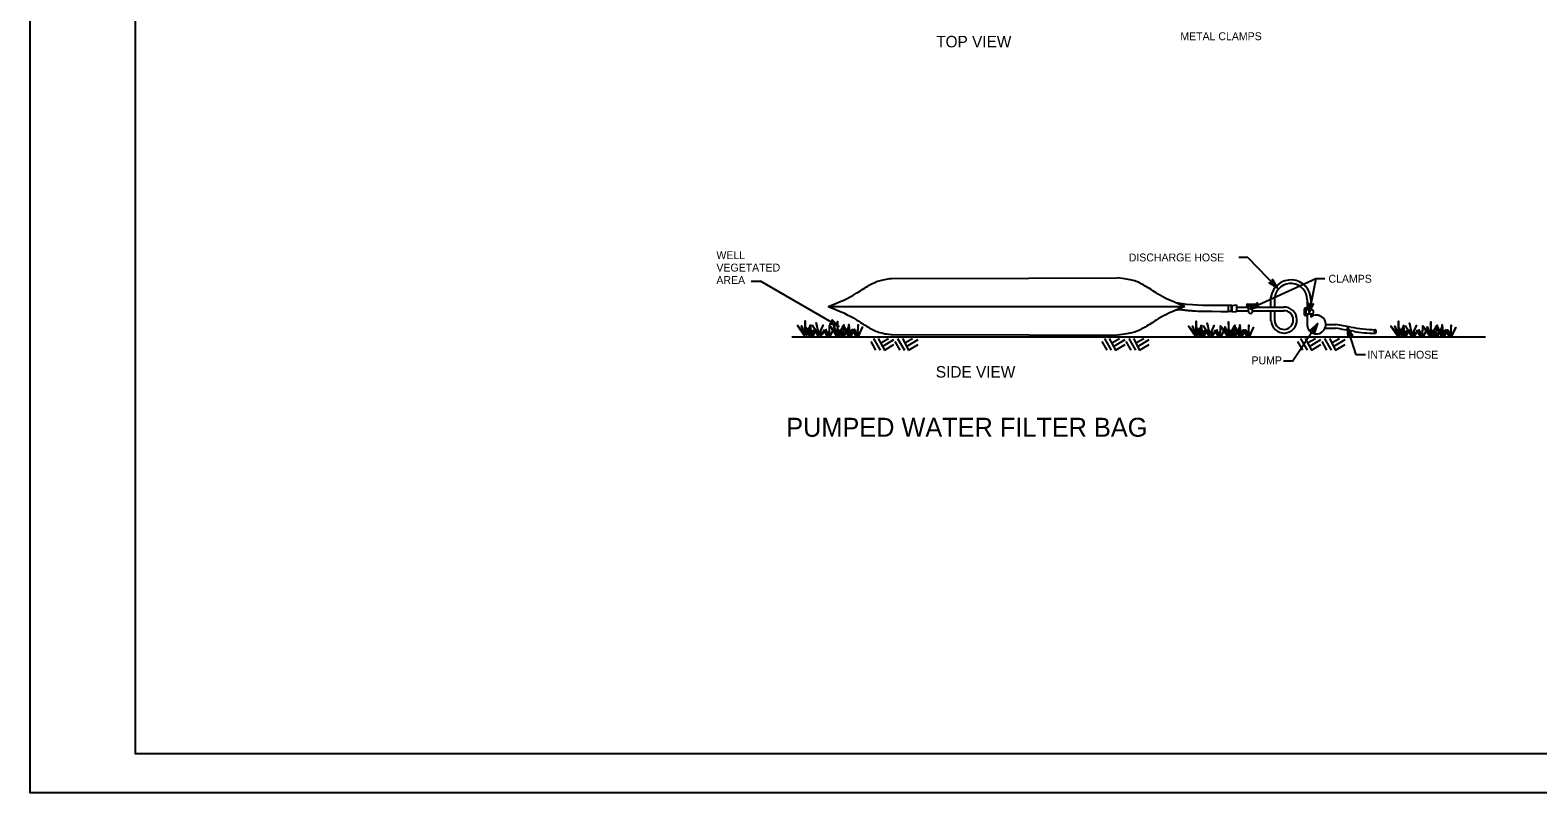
# Model space of a CAD drawing. Extents: x 636462 to 637367, y 299944 to 300538.
# Drawn here: x 636462 to 637035, y 299944 to 300234 of the extents above; entities that cross this region are included whole.
import ezdxf

# ---------------------------------------------------------------- set-up
doc = ezdxf.new("R2010")
doc.units = 0
for name, color, linetype in [('1', 7, 'Continuous'), ('Default', 7, 'Continuous'), ('PLT-BNDY', 7, 'Continuous')]:
    doc.layers.add(name, color=color, linetype=linetype)

# ---------------------------------------------------------------- blocks, each defined once
blk = doc.blocks.new('Group3')
at = {"layer": 'Default'}
for points in [[(7.465, 1.976), (7.424, 2.068), (7.472, 1.977), (7.471, 2.092), (7.483, 1.978), (7.502, 2.036), (7.488, 1.979), (7.531, 2.043), (7.493, 1.975)], [(7.572, 1.973), (7.633, 2.048), (7.566, 1.995), (7.605, 2.091), (7.56, 2.006), (7.533, 2.117), (7.558, 1.989), (7.492, 2.087), (7.553, 1.975)], [(7.676, 1.975), (7.717, 2.064), (7.668, 1.974), (7.669, 2.089), (7.657, 1.975), (7.638, 2.033), (7.652, 1.976), (7.609, 2.04), (7.645, 1.975)], [(7.765, 1.976), (7.809, 2.085), (7.757, 1.996), (7.753, 2.131), (7.749, 2.007), (7.714, 2.078), (7.749, 1.989), (7.674, 2.081), (7.745, 1.976)]]:
    blk.add_lwpolyline(points, dxfattribs=at)

msp = doc.modelspace()

# ---------------------------------------------------------------- linework, layer by layer
at = {"layer": '1'}
msp.add_lwpolyline([(637287.91, 299959.45), (637287.91, 300523.45), (636501.91, 300523.45), (636501.91, 299959.45), (637287.91, 299959.45), (637287.91, 299985.81), (637087.91, 299985.81), (637087.91, 300050.49), (637287.91, 300050.49), (637287.91, 300079.45), (637087.91, 300079.45), (637087.91, 299959.45), (637166.72, 299959.45), (637166.72, 299985.81), (637166.72, 299959.45), (637243.72, 299959.45), (637243.72, 299985.81), (637243.72, 299973.49), (637287.91, 299973.49)], dxfattribs=at)
at = {"layer": 'Default'}
for p, q in [((636925.21, 300148.01), (636921.71, 300148.01)), ((636925.21, 300148.01), (636936.36, 300136.51)), ((636789.69, 300140.04), (636841.86, 300140.08)), ((636841.86, 300140.18), (636875.4, 300140.21)), ((636950.99, 300139.92), (636926.11, 300128.42)), ((636950.99, 300139.92), (636948.51, 300127.07)), ((636954.49, 300139.92), (636950.99, 300139.92)), ((636736.26, 300138.96), (636739.76, 300138.96)), ((636769.63, 300121.8), (636739.76, 300138.96)), ((636765.53, 300129.36), (636841.87, 300129.36)), ((636841.87, 300129.36), (636901.24, 300129.36)), ((636901.79, 300130.18), (636897.93, 300130.72)), ((636904.1, 300129.98), (636901.79, 300130.18)), ((636908.05, 300129.72), (636904.1, 300129.98)), ((636917.64, 300129.72), (636908.05, 300129.72)), ((636919.11, 300129.72), (636917.64, 300129.72)), ((636917.67, 300129.72), (636917.67, 300127.5)), ((636918.86, 300129.72), (636918.86, 300127.5)), ((636919.11, 300129.72), (636920.81, 300129.94)), ((636919.14, 300129.73), (636919.14, 300127.5)), ((636920.81, 300129.16), (636925.41, 300129.16)), ((636920.85, 300129.94), (636920.85, 300127.29)), ((636924.7, 300129.87), (636924.7, 300129.92)), ((636925.03, 300130.24), (636927.35, 300130.24)), ((636925.41, 300129.55), (636925.03, 300129.55)), ((636925.41, 300127.5), (636925.41, 300129.55)), ((636925.41, 300129.55), (636926.97, 300129.55)), ((636926.97, 300127.5), (636926.97, 300129.55)), ((636927.35, 300129.55), (636926.97, 300129.55)), ((636926.97, 300129.16), (636938.84, 300129.16)), ((636927.67, 300129.87), (636927.67, 300129.92)), ((636933.98, 300129.16), (636933.98, 300132.91)), ((636935.38, 300129.16), (636935.38, 300133.01)), ((636946.72, 300126.13), (636946.72, 300128.45)), ((636947.41, 300128.45), (636947.41, 300128.06)), ((636947.74, 300131.84), (636947.74, 300128.06)), ((636949.14, 300131.84), (636949.14, 300128.06)), ((636919.14, 300127.5), (636917.67, 300127.5)), ((636919.14, 300127.5), (636920.85, 300127.29)), ((636920.85, 300127.76), (636925.41, 300127.76)), ((636926.16, 300126.75), (636926.22, 300126.75)), ((636926.97, 300127.76), (636938.84, 300127.76)), ((636933.98, 300123.87), (636933.98, 300127.76)), ((636935.38, 300123.97), (636935.38, 300127.76)), ((636942.21, 300108.61), (636951.63, 300122.9)), ((636947.41, 300126.51), (636947.41, 300128.06)), ((636949.46, 300128.06), (636947.41, 300128.06)), ((636949.46, 300126.51), (636947.41, 300126.51)), ((636947.41, 300126.51), (636947.41, 300126.13)), ((636947.74, 300126.51), (636947.74, 300122.21)), ((636949.14, 300126.51), (636949.14, 300125.36)), ((636751.72, 300117.79), (637015.53, 300117.79)), ((636782.75, 300117.19), (636785.27, 300112.79)), ((636782.75, 300117.19), (636785.27, 300112.79)), ((636784.55, 300117.19), (636786.95, 300112.79)), ((636784.55, 300117.19), (636786.95, 300112.79)), ((636785.5, 300115.51), (636788.45, 300117.19)), ((636785.5, 300115.51), (636788.45, 300117.19)), ((636789.69, 300118.67), (636841.86, 300118.63)), ((636791.92, 300117.19), (636794.49, 300112.79)), ((636791.92, 300117.19), (636794.49, 300112.79)), ((636793.77, 300117.19), (636796.09, 300112.79)), ((636793.77, 300117.19), (636796.09, 300112.79)), ((636794.64, 300115.51), (636797.64, 300117.19)), ((636794.64, 300115.51), (636797.64, 300117.19)), ((636841.86, 300118.63), (636875.4, 300118.51)), ((636870.67, 300117.19), (636873.2, 300112.79)), ((636870.67, 300117.19), (636873.2, 300112.79)), ((636872.47, 300117.19), (636874.87, 300112.79)), ((636872.47, 300117.19), (636874.87, 300112.79)), ((636873.42, 300115.51), (636876.37, 300117.19)), ((636873.42, 300115.51), (636876.37, 300117.19)), ((636879.84, 300117.19), (636882.41, 300112.79)), ((636879.84, 300117.19), (636882.41, 300112.79)), ((636881.69, 300117.19), (636884.01, 300112.79)), ((636881.69, 300117.19), (636884.01, 300112.79)), ((636882.56, 300115.51), (636885.56, 300117.19)), ((636882.56, 300115.51), (636885.56, 300117.19)), ((636945.17, 300117.19), (636947.69, 300112.79)), ((636945.17, 300117.19), (636947.69, 300112.79)), ((636946.96, 300117.19), (636949.36, 300112.79)), ((636946.96, 300117.19), (636949.36, 300112.79)), ((636947.91, 300115.51), (636950.86, 300117.19)), ((636947.91, 300115.51), (636950.86, 300117.19)), ((636954.33, 300117.19), (636956.91, 300112.79)), ((636954.33, 300117.19), (636956.91, 300112.79)), ((636954.56, 300121.18), (636958.51, 300121.08)), ((636954.82, 300122.57), (636958.63, 300122.48)), ((636956.18, 300117.19), (636958.51, 300112.79)), ((636956.18, 300117.19), (636958.51, 300112.79)), ((636957.06, 300115.51), (636960.06, 300117.19)), ((636957.06, 300115.51), (636960.06, 300117.19)), ((636966.38, 300111.04), (636963.13, 300121.32)), ((636781.7, 300116.01), (636783.55, 300112.79)), ((636781.7, 300116.01), (636783.55, 300112.79)), ((636786.17, 300114.16), (636790.55, 300116.76)), ((636786.17, 300114.16), (636790.55, 300116.76)), ((636786.95, 300112.79), (636790.55, 300114.94)), ((636786.95, 300112.79), (636790.55, 300114.94)), ((636790.85, 300116.01), (636792.72, 300112.79)), ((636790.85, 300116.01), (636792.72, 300112.79)), ((636795.37, 300114.16), (636799.74, 300116.76)), ((636795.37, 300114.16), (636799.74, 300116.76)), ((636796.09, 300112.79), (636799.74, 300114.94)), ((636796.09, 300112.79), (636799.74, 300114.94)), ((636869.62, 300116.01), (636871.47, 300112.79)), ((636869.62, 300116.01), (636871.47, 300112.79)), ((636874.09, 300114.16), (636878.47, 300116.76)), ((636874.09, 300114.16), (636878.47, 300116.76)), ((636874.87, 300112.79), (636878.47, 300114.94)), ((636874.87, 300112.79), (636878.47, 300114.94)), ((636878.77, 300116.01), (636880.64, 300112.79)), ((636878.77, 300116.01), (636880.64, 300112.79)), ((636883.29, 300114.16), (636887.66, 300116.76)), ((636883.29, 300114.16), (636887.66, 300116.76)), ((636884.01, 300112.79), (636887.66, 300114.94)), ((636884.01, 300112.79), (636887.66, 300114.94)), ((636944.12, 300116.01), (636945.96, 300112.79)), ((636944.12, 300116.01), (636945.96, 300112.79)), ((636948.59, 300114.16), (636952.96, 300116.76)), ((636948.59, 300114.16), (636952.96, 300116.76)), ((636949.36, 300112.79), (636952.96, 300114.94)), ((636949.36, 300112.79), (636952.96, 300114.94)), ((636953.26, 300116.01), (636955.13, 300112.79)), ((636953.26, 300116.01), (636955.13, 300112.79)), ((636957.78, 300114.16), (636962.15, 300116.76)), ((636957.78, 300114.16), (636962.15, 300116.76)), ((636958.51, 300112.79), (636962.15, 300114.94)), ((636958.51, 300112.79), (636962.15, 300114.94)), ((636942.21, 300108.61), (636938.71, 300108.61)), ((636969.88, 300111.04), (636966.38, 300111.04))]:
    msp.add_line(p, q, dxfattribs=at)
for points in [[(636934.54, 300139.26), (636934.51, 300139.61), (636936.36, 300136.51), (636934.54, 300139.26), (636934.42, 300138.86), (636936.36, 300136.51), (636934.05, 300138.48), (636933.65, 300138.35), (636936.36, 300136.51), (636933.27, 300138.37), (636933.65, 300138.35)], [(636765.53, 300129.36), (636767.84, 300128.44), (636769.79, 300127.63), (636771.42, 300126.9), (636772.78, 300126.25), (636773.92, 300125.66), (636774.88, 300125.13), (636775.7, 300124.64), (636776.44, 300124.18), (636777.13, 300123.74), (636777.79, 300123.33), (636778.41, 300122.94), (636779, 300122.57), (636779.57, 300122.22), (636780.11, 300121.88), (636780.64, 300121.57), (636781.15, 300121.27), (636781.64, 300120.98), (636782.13, 300120.72), (636782.62, 300120.47), (636783.11, 300120.23), (636783.61, 300120.01), (636784.12, 300119.81), (636784.65, 300119.63), (636785.2, 300119.46), (636785.79, 300119.3), (636786.4, 300119.16), (636787.07, 300119.03), (636787.79, 300118.92), (636788.57, 300118.81), (636789.42, 300118.7), (636789.69, 300118.67)], [(636929.3, 300129.22), (636929.64, 300129.13), (636926.11, 300128.42), (636929.3, 300129.22), (636928.97, 300129.47), (636926.11, 300128.42), (636928.74, 300129.94), (636928.74, 300130.36), (636926.11, 300128.42), (636928.89, 300130.71), (636928.74, 300130.36)], [(636949.73, 300130.13), (636949.99, 300130.35), (636948.51, 300127.07), (636949.73, 300130.13), (636949.32, 300130), (636948.51, 300127.07), (636948.81, 300130.09), (636948.47, 300130.34), (636948.51, 300127.07), (636948.27, 300130.67), (636948.47, 300130.34)], [(636757.21, 300118.21), (636758.87, 300122.26), (636756.93, 300118.98), (636756.78, 300123.96), (636756.64, 300119.37), (636755.35, 300122), (636756.65, 300118.72), (636753.89, 300122.11), (636756.49, 300118.22)], [(636767.15, 300123.97), (636767.03, 300124.29), (636769.63, 300121.8), (636767.15, 300123.97), (636767.14, 300123.54), (636769.63, 300121.8), (636766.88, 300123.09), (636766.54, 300122.85), (636769.63, 300121.8), (636766.16, 300122.78), (636766.54, 300122.85)], [(636897.93, 300128.03), (636898.05, 300128.06), (636898.16, 300128.08), (636898.27, 300128.11), (636898.37, 300128.13), (636898.47, 300128.15), (636898.56, 300128.16), (636898.64, 300128.18), (636898.73, 300128.19), (636898.8, 300128.2), (636898.88, 300128.21), (636898.95, 300128.22), (636899.02, 300128.23), (636899.09, 300128.24), (636899.15, 300128.24), (636899.22, 300128.24), (636899.28, 300128.25), (636899.35, 300128.25), (636899.42, 300128.24), (636899.5, 300128.24), (636899.58, 300128.24), (636899.68, 300128.23), (636899.79, 300128.22), (636899.92, 300128.2), (636900.07, 300128.18), (636900.24, 300128.16), (636900.43, 300128.14), (636900.64, 300128.11), (636900.86, 300128.08), (636901.1, 300128.05), (636901.35, 300128.02), (636901.61, 300127.99), (636901.88, 300127.96), (636902.15, 300127.93), (636902.44, 300127.9), (636902.74, 300127.87), (636903.06, 300127.84), (636903.42, 300127.81), (636903.81, 300127.78), (636904.25, 300127.75), (636904.74, 300127.71), (636905.31, 300127.68), (636906.1, 300127.64), (636907.29, 300127.6), (636909.04, 300127.57), (636911.52, 300127.54), (636914.89, 300127.51), (636917.67, 300127.5)], [(636905.97, 300118.05), (636907.62, 300122.09), (636905.68, 300118.81), (636905.54, 300123.79), (636905.39, 300119.21), (636904.11, 300121.83), (636905.4, 300118.56), (636902.64, 300121.94), (636905.25, 300118.05)], [(636949.36, 300120.52), (636949.03, 300120.41), (636951.63, 300122.9), (636949.36, 300120.52), (636949.78, 300120.48), (636951.63, 300122.9), (636950.23, 300120.21), (636950.45, 300119.85), (636951.63, 300122.9), (636950.51, 300119.48), (636950.45, 300119.85)], [(636982.89, 300118.05), (636984.54, 300122.09), (636982.6, 300118.81), (636982.46, 300123.79), (636982.32, 300119.21), (636981.03, 300121.83), (636982.32, 300118.56), (636979.57, 300121.94), (636982.17, 300118.05)], [(636771.77, 300118.26), (636773.26, 300121.55), (636771.45, 300118.21), (636771.5, 300122.45), (636771.05, 300118.24), (636770.36, 300120.37), (636770.88, 300118.28), (636769.29, 300120.65), (636770.62, 300118.25)], [(636773.12, 300118.25), (636771.6, 300121.64), (636773.4, 300118.3), (636773.37, 300122.54), (636773.79, 300118.32), (636774.49, 300120.45), (636773.97, 300118.36), (636775.57, 300120.72), (636774.16, 300118.21)], [(636777.12, 300118.26), (636778.61, 300121.55), (636776.8, 300118.21), (636776.86, 300122.45), (636776.4, 300118.24), (636775.71, 300120.37), (636776.23, 300118.28), (636774.64, 300120.65), (636775.98, 300118.25)], [(636920.52, 300118.09), (636922.02, 300121.38), (636920.2, 300118.05), (636920.26, 300122.29), (636919.81, 300118.07), (636919.12, 300120.21), (636919.63, 300118.11), (636918.05, 300120.48), (636919.38, 300118.08)], [(636921.88, 300118.08), (636920.36, 300121.48), (636922.15, 300118.13), (636922.12, 300122.37), (636922.55, 300118.15), (636923.25, 300120.28), (636922.72, 300118.19), (636924.32, 300120.55), (636922.91, 300118.05)], [(636925.87, 300118.09), (636927.37, 300121.38), (636925.55, 300118.05), (636925.61, 300122.29), (636925.16, 300118.07), (636924.47, 300120.21), (636924.98, 300118.11), (636923.4, 300120.48), (636924.73, 300118.08)], [(636963.48, 300118.04), (636963.34, 300117.72), (636963.13, 300121.32), (636963.48, 300118.04), (636963.78, 300118.34), (636963.13, 300121.32), (636964.27, 300118.5), (636964.69, 300118.43), (636963.13, 300121.32), (636965.01, 300118.24), (636964.69, 300118.43)], [(636997.44, 300118.09), (636998.94, 300121.38), (636997.12, 300118.05), (636997.18, 300122.29), (636996.73, 300118.07), (636996.04, 300120.21), (636996.55, 300118.11), (636994.97, 300120.48), (636996.3, 300118.08)], [(636998.8, 300118.08), (636997.28, 300121.48), (636999.07, 300118.13), (636999.04, 300122.37), (636999.47, 300118.15), (637000.17, 300120.28), (636999.64, 300118.19), (637001.24, 300120.55), (636999.83, 300118.05)], [(637002.8, 300118.09), (637004.29, 300121.38), (637002.47, 300118.05), (637002.53, 300122.29), (637002.08, 300118.07), (637001.39, 300120.21), (637001.9, 300118.11), (637000.32, 300120.48), (637001.65, 300118.08)]]:
    msp.add_lwpolyline(points, dxfattribs=at)
for centre, radius, start, end in [((636941.52, 300131.85), 7.62, 359.96051, 171.95351), ((636941.51, 300131.85), 6.24, 359.93949, 169.27656), ((636925.03, 300129.92), 0.325, 90, 180), ((636925.03, 300129.87), 0.325, 180, 270), ((636927.35, 300129.92), 0.325, 360, 90), ((636927.35, 300129.87), 0.325, 270, 0), ((636938.92, 300124.22), 4.95, 183.97483, 91.25762), ((636947.04, 300128.45), 0.325, 90, 180), ((636947.09, 300128.45), 0.325, 360, 90), ((636926.16, 300127.5), 0.75, 180, 270), ((636926.22, 300127.5), 0.75, 270, 0), ((636938.92, 300124.22), 3.55, 183.97483, 91.25762), ((636947.04, 300126.13), 0.325, 180, 270), ((636947.09, 300126.13), 0.325, 270, 0), ((636951.27, 300122.52), 3.55, 183.97483, 127.00163), ((636949.46, 300127.31), 0.75, 360, 90), ((636949.46, 300127.26), 0.75, 270, 360), ((636926.61, 299910.74), 212.74, 79.51504, 81.37638), ((636926.61, 299910.74), 214.14, 79.84955, 81.40009), ((636974.6, 300174.4), 53.86, 259.02396, 268.98442), ((636974.6, 300174.4), 55.26, 260.33279, 268.98442)]:
    msp.add_arc(centre, radius, start, end, dxfattribs=at)
msp.add_ellipse((636973.64, 300119.86), major_axis=(-0.012, -0.699), ratio=0.344138, dxfattribs=at)
for points in [[(636765.53, 300129.36), (636772.21, 300131.93), (636776.87, 300134.77), (636781.28, 300137.62), (636784.64, 300139.3), (636787.77, 300139.83), (636789.69, 300140.04)], [(636901.24, 300129.36), (636894.56, 300131.93), (636889.9, 300134.77), (636885.5, 300137.62), (636881.87, 300139.43), (636878.24, 300139.95), (636875.4, 300140.21)], [(636901.24, 300129.36), (636894.56, 300126.79), (636889.9, 300123.94), (636885.5, 300121.09), (636881.87, 300119.28), (636878.24, 300118.77), (636875.4, 300118.51)]]:
    msp.add_open_spline(points, degree=3, dxfattribs=at)
at = {"layer": 'PLT-BNDY'}
msp.add_lwpolyline([(636461.91, 300538.45), (637302.91, 300538.45), (637302.91, 299944.45), (636461.91, 299944.45)], close=True, dxfattribs=at)

# ---------------------------------------------------------------- block references
at = {"layer": 'Default', "xscale": 36.88524000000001, "yscale": 36.88524000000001}
for p in [(636483.15, 300045.12), (636631.9, 300044.95), (636708.82, 300044.95)]:
    msp.add_blockref('Group3', p, dxfattribs=at)

# ---------------------------------------------------------------- texts
at = {"layer": 'Default'}
for s, height, p in [('TOP VIEW', 4.372, (636806.61, 300227.89)), ('METAL CLAMPS ', 2.998, (636899.48, 300230.62)), ('WELL', 2.998, (636722.99, 300147.4)), ('VEGETATED', 2.998, (636722.99, 300142.66)), ('DISCHARGE HOSE', 2.998, (636879.86, 300146.51)), ('AREA', 2.998, (636722.99, 300137.91)), ('CLAMPS', 2.998, (636955.84, 300138.42)), ('INTAKE HOSE', 2.998, (636970.68, 300109.54)), ('SIDE VIEW', 4.372, (636806.48, 300102.33)), ('PUMP', 2.998, (636926.55, 300107.38)), ('PUMPED WATER FILTER BAG', 7.1953, (636749.57, 300079.85))]:
    msp.add_text(s, height=height, dxfattribs=at).set_placement(p)

doc.saveas('drawing.dxf')
